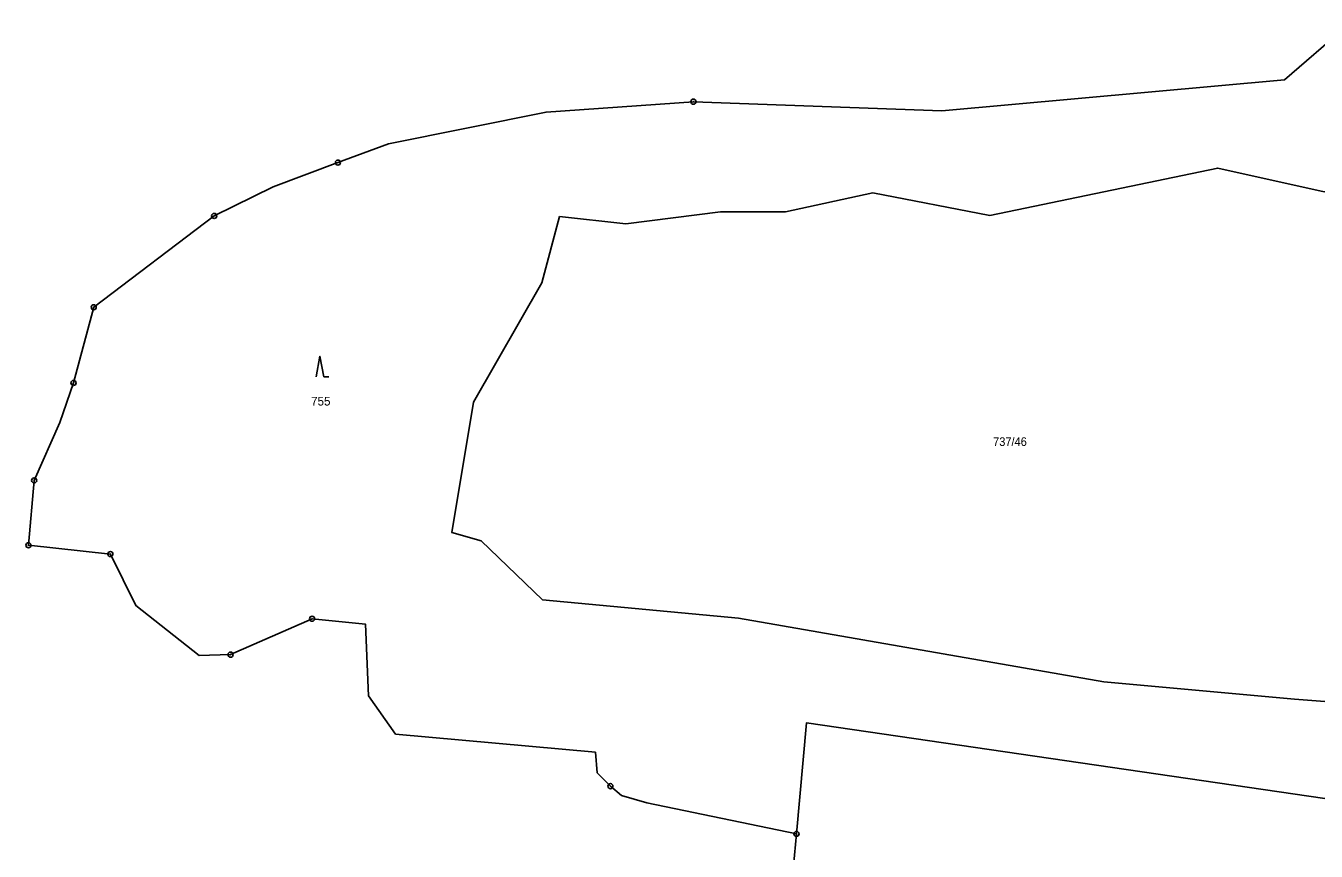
# Model space of a CAD drawing. Extents: x -687135 to -684370, y -1007309 to -1005782.
# Drawn here: x -687135.1 to -686882.4, y -1006425.4 to -1006263.8 of the extents above; entities that cross this region are included whole.
import ezdxf

# ---------------------------------------------------------------- set-up
doc = ezdxf.new("R2010")
doc.units = 0
doc.header["$LTSCALE"] = 0.68
for name, color, linetype, lineweight in [('1', 7, 'Continuous', 25), ('3', 7, 'Continuous', 25), ('8', 7, 'Continuous', 25)]:
    doc.layers.add(name, color=color, linetype=linetype, lineweight=lineweight)
doc.layers.add('2', color=7, linetype='Continuous')

msp = doc.modelspace()

# ---------------------------------------------------------------- linework, layer by layer
at = {"layer": '1'}
for p, q in [((-686876.35, -1006263.75), (-686888.56, -1006274.33)), ((-687013.49, -1006415.94), (-686984.16, -1006422.05)), ((-686984.16, -1006422.05), (-686984.76, -1006428.31))]:
    msp.add_line(p, q, dxfattribs=at)
for points in [[(-686888.56, -1006274.33), (-686955.68, -1006280.41), (-687004.34, -1006278.61), (-687033.2, -1006280.66), (-687064.05, -1006286.86)], [(-686856.22, -1006398.01), (-686886.59, -1006395.67), (-686923.95, -1006392.28), (-686995.5, -1006379.79), (-687033.91, -1006376.19), (-687045.92, -1006364.66), (-687051.68, -1006362.98), (-687047.45, -1006337.49), (-687034.02, -1006314.1), (-687030.55, -1006301.13), (-687017.58, -1006302.52), (-686999.06, -1006300.2), (-686986.32, -1006300.2), (-686969.19, -1006296.5), (-686946.27, -1006300.9), (-686901.65, -1006291.63), (-686880.81, -1006296.26), (-686863.68, -1006295.8), (-686855.34, -1006283.06)], [(-687064.05, -1006286.86), (-687073.98, -1006290.55), (-687086.64, -1006295.32), (-687098.21, -1006301), (-687121.81, -1006318.88), (-687125.76, -1006333.71)], [(-687125.76, -1006333.71), (-687128.45, -1006341.46), (-687133.47, -1006352.8)], [(-687133.47, -1006352.8), (-687134.61, -1006365.5), (-687118.55, -1006367.23)], [(-687118.55, -1006367.23), (-687113.56, -1006377.31), (-687101.17, -1006387.1), (-687095, -1006386.93), (-687079.04, -1006379.89)], [(-687079.04, -1006379.89), (-687068.6, -1006380.95), (-687068.01, -1006394.97), (-687062.67, -1006402.49), (-687023.51, -1006406)], [(-686862.81, -1006417.73), (-686982.17, -1006400.27), (-686984.16, -1006422.05)], [(-687023.51, -1006406), (-687023.18, -1006410.09), (-687020.61, -1006412.69), (-687018.42, -1006414.52), (-687013.49, -1006415.94)]]:
    msp.add_lwpolyline(points, dxfattribs=at)
at = {"layer": '3'}
msp.add_line((-687076.76, -1006332.49), (-687075.764, -1006332.49), dxfattribs=at)
msp.add_lwpolyline([(-687076.76, -1006332.49), (-687077.51, -1006328.49), (-687078.26, -1006332.49)], dxfattribs=at)
at = {"layer": '8'}
for centre, radius in [((-687004.34, -1006278.6099), 0.5), ((-687004.34, -1006278.6099), 0.0303), ((-687073.98, -1006290.5499), 0.5), ((-687073.98, -1006290.5499), 0.0303), ((-687098.21, -1006300.9999), 0.5), ((-687098.21, -1006300.9999), 0.0303), ((-687121.81, -1006318.8799), 0.5), ((-687121.81, -1006318.8799), 0.0303), ((-687125.76, -1006333.7099), 0.5), ((-687125.76, -1006333.7099), 0.0303), ((-687133.47, -1006352.7999), 0.5), ((-687133.47, -1006352.7999), 0.0303), ((-687134.61, -1006365.4999), 0.5), ((-687134.61, -1006365.4999), 0.0303), ((-687118.55, -1006367.2299), 0.5), ((-687118.55, -1006367.2299), 0.0303), ((-687079.04, -1006379.8899), 0.5), ((-687079.04, -1006379.8899), 0.0303), ((-687095, -1006386.9299), 0.5), ((-687095, -1006386.9299), 0.0303), ((-687020.61, -1006412.6899), 0.5), ((-687020.61, -1006412.6899), 0.0303), ((-686984.16, -1006422.0499), 0.5), ((-686984.16, -1006422.0499), 0.0303)]:
    msp.add_circle(centre, radius, dxfattribs=at)

# ---------------------------------------------------------------- texts
at = {"layer": '2'}
msp.add_text('755', height=1.7, dxfattribs=at).set_placement((-687079.23, -1006338.13))
at = {"layer": '2', "width": 0.95}
msp.add_text('737/46', height=1.7, dxfattribs=at).set_placement((-686945.65, -1006346.059))

doc.saveas('drawing.dxf')
